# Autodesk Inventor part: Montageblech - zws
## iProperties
Created: 2005-10
Part Number: Montageblech - zws
Document SubType Name: Modeling
Designer: li
Manufacturer: Standard
Standards Organization: Custom
Density: 1 g/cm^3
Author: li
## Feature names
1. Extrusion1
2. Rundung1 [Fillet]
